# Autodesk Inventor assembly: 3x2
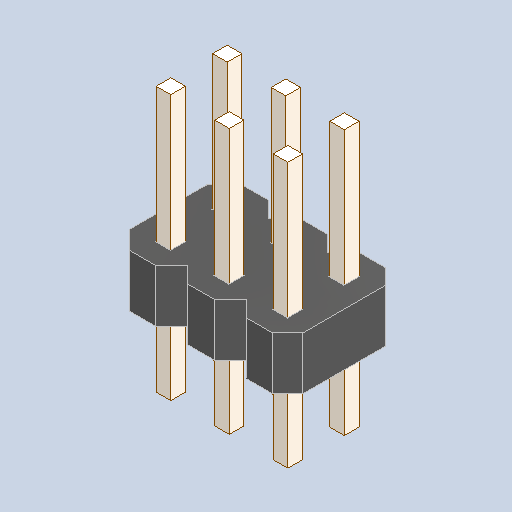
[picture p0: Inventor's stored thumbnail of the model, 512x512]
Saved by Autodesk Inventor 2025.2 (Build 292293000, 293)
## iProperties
Created: 2025-04
Part Number: 3x2
Description: PART--DESC
Document SubType Name: Assembly
Designer: BennF
Author: BennF
Revision Number: NONE
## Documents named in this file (3)
- C:\Users\BennF\Nextcloud\Benutzer\CNC JarBeRi\existing parts\Electronics\RepRap A4988 Shied (USE WITHOUT ARDUINO)\reprap-a4988-1.snapshot.1\RepRap\RepRap\3x2.iam
- C:\Users\BennF\Nextcloud\Benutzer\CNC JarBeRi\existing parts\Electronics\RepRap A4988 Shied (USE WITHOUT ARDUINO)\reprap-a4988-1.snapshot.1\RepRap\RepRap\3x2 Geometry.ipt
- C:\Users\BennF\Nextcloud\Benutzer\CNC JarBeRi\existing parts\Electronics\RepRap A4988 Shied (USE WITHOUT ARDUINO)\reprap-a4988-1.snapshot.1\RepRap\RepRap\pin10.ipt
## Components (2 placed, 2 different names)
1. 3x2 Geometry
2. pin10
